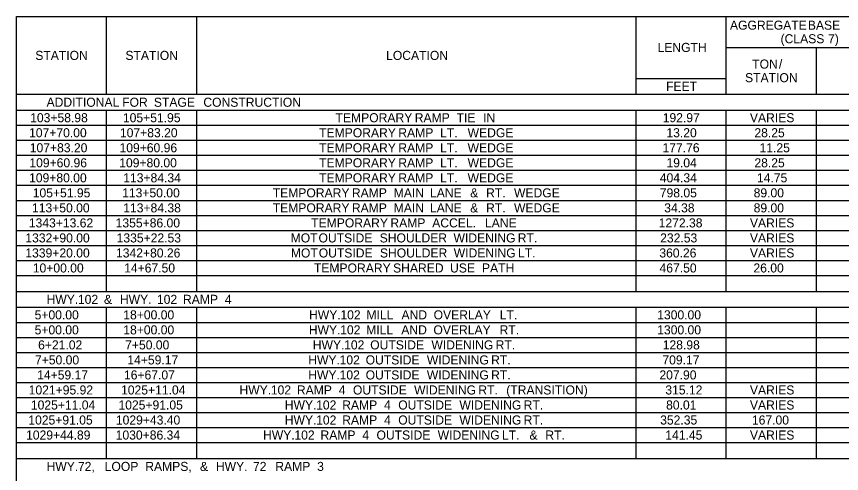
# Model space of a CAD drawing. Extents: x 1226567 to 1228151, y 151309 to 152305.
# Drawn here: x 1226566.8 to 1226930.3, y 152053.3 to 152254.7 of the extents above; entities that cross this region are included whole.
import ezdxf

# ---------------------------------------------------------------- set-up
doc = ezdxf.new("R2010")
doc.units = 0
doc.layers.add('R_Dimension', color=7, linetype='Continuous')

msp = doc.modelspace()

# ---------------------------------------------------------------- linework, layer by layer
at = {"layer": 'R_Dimension'}
for p, q in [((1226566.84, 152254.68), (1228150.79, 152254.68)), ((1226566.84, 151664.64), (1226566.84, 152254.68)), ((1226606.57, 152220.4), (1226606.57, 152254.68)), ((1226646.29, 152220.4), (1226646.29, 152254.68)), ((1226839.86, 152220.4), (1226839.86, 152254.68)), ((1226879.58, 152220.4), (1226879.58, 152254.68)), ((1226879.58, 152241.04), (1228150.79, 152241.04)), ((1226919.31, 152220.4), (1226919.31, 152241.04)), ((1226839.86, 152227.41), (1226879.58, 152227.41)), ((1226566.84, 152220.4), (1228150.79, 152220.4)), ((1226566.84, 152220.4), (1228150.79, 152220.4)), ((1226879.58, 152220.4), (1226998.76, 152220.4)), ((1226566.84, 152213.39), (1228150.79, 152213.39)), ((1226606.57, 152133.55), (1226606.57, 152213.39)), ((1226646.29, 152133.55), (1226646.29, 152213.39)), ((1226839.86, 152133.55), (1226839.86, 152213.39)), ((1226879.58, 152133.55), (1226879.58, 152213.39)), ((1226919.31, 152133.55), (1226919.31, 152213.39)), ((1226566.84, 152206.77), (1228150.79, 152206.77)), ((1226566.84, 152200.15), (1228150.79, 152200.15)), ((1226566.84, 152193.53), (1228150.79, 152193.53)), ((1226566.84, 152186.91), (1228150.79, 152186.91)), ((1226566.84, 152180.29), (1228150.79, 152180.29)), ((1226566.84, 152173.67), (1228150.79, 152173.67)), ((1226566.84, 152167.05), (1228150.79, 152167.05)), ((1226566.84, 152160.43), (1228150.79, 152160.43)), ((1226566.84, 152153.8), (1228150.79, 152153.8)), ((1226566.84, 152147.18), (1228150.79, 152147.18)), ((1226566.84, 152140.56), (1228150.79, 152140.56)), ((1226566.84, 152133.55), (1228150.79, 152133.55)), ((1226566.84, 152126.54), (1228150.79, 152126.54)), ((1226606.57, 152059.94), (1226606.57, 152126.54)), ((1226646.29, 152059.94), (1226646.29, 152126.54)), ((1226839.86, 152059.94), (1226839.86, 152126.54)), ((1226879.58, 152059.94), (1226879.58, 152126.54)), ((1226919.31, 152059.94), (1226919.31, 152126.54)), ((1226566.84, 152119.92), (1228150.79, 152119.92)), ((1226566.84, 152113.3), (1228150.79, 152113.3)), ((1226566.84, 152106.68), (1228150.79, 152106.68)), ((1226566.84, 152100.06), (1228150.79, 152100.06)), ((1226566.84, 152093.44), (1228150.79, 152093.44)), ((1226566.84, 152086.82), (1228150.79, 152086.82)), ((1226566.84, 152080.2), (1228150.79, 152080.2)), ((1226566.84, 152073.58), (1228150.79, 152073.58)), ((1226566.84, 152066.95), (1228150.79, 152066.95)), ((1226566.84, 152059.94), (1228150.79, 152059.94))]:
    msp.add_line(p, q, dxfattribs=at)

# ---------------------------------------------------------------- texts
for s, height, p in [('AGGREGATE', 3.994, (1226881.19, 152248.86)), (' BASE', 3.994, (1226914.02, 152248.86)), ('(CLASS', 3.994, (1226903.49, 152242.87)), (' 7)', 3.994, (1226922.92, 152242.87)), ('LENGTH', 3.994, (1226849.28, 152239.05)), ('STATION', 3.994, (1226575.12, 152235.54)), ('STATION', 3.994, (1226614.84, 152235.54)), ('LOCATION', 3.994, (1226729.69, 152235.54)), ('TON', 3.994, (1226891, 152231.72)), (' /', 3.994, (1226901.28, 152231.72)), ('STATION', 3.994, (1226887.85, 152225.73)), ('FEET', 3.994, (1226853.04, 152221.91)), ('ADDITIONAL', 3.994, (1226580.09, 152214.9)), (' FOR', 3.994, (1226611.92, 152214.9)), (' STAGE', 3.994, (1226625.88, 152214.9)), (' CONSTRUCTION', 3.9945, (1226647.68, 152214.9)), ('103+58.98', 3.994, (1226572.87, 152208.08)), ('105+51.95', 3.994, (1226613.73, 152208.08)), ('TEMPORARY', 3.994, (1226707.42, 152208.08)), (' RAMP', 3.994, (1226740.83, 152208.08)), (' TIE', 3.994, (1226759.26, 152208.08)), (' IN', 3.994, (1226770.93, 152208.08)), ('192.97', 3.994, (1226851.57, 152208.08)), ('VARIES', 3.994, (1226889.98, 152208.08)), ('107+70.00', 3.994, (1226572.38, 152201.46)), ('107+83.20', 3.994, (1226612.42, 152201.46)), ('TEMPORARY', 3.994, (1226700.17, 152201.46)), (' RAMP', 3.994, (1226733.58, 152201.46)), (' LT.', 3.994, (1226752.01, 152201.46)), (' WEDGE', 3.994, (1226764.12, 152201.46)), ('13.20', 3.994, (1226853.19, 152201.46)), ('28.25', 3.994, (1226891.96, 152201.46)), ('107+83.20', 3.994, (1226572.69, 152194.84)), ('109+60.96', 3.994, (1226612.23, 152194.84)), ('TEMPORARY', 3.994, (1226700.17, 152194.84)), (' RAMP', 3.994, (1226733.58, 152194.84)), (' LT.', 3.994, (1226752.01, 152194.84)), (' WEDGE', 3.994, (1226764.12, 152194.84)), ('177.76', 3.994, (1226851.46, 152194.84)), ('11.25', 3.994, (1226894.22, 152194.84)), ('109+60.96', 3.994, (1226572.51, 152188.22)), ('109+80.00', 3.994, (1226612.11, 152188.22)), ('TEMPORARY', 3.994, (1226700.17, 152188.22)), (' RAMP', 3.994, (1226733.58, 152188.22)), (' LT.', 3.994, (1226752.01, 152188.22)), (' WEDGE', 3.994, (1226764.12, 152188.22)), ('19.04', 3.994, (1226853.21, 152188.22)), ('28.25', 3.994, (1226891.96, 152188.22)), ('109+80.00', 3.994, (1226572.38, 152181.6)), ('113+84.34', 3.994, (1226613.88, 152181.6)), ('TEMPORARY', 3.994, (1226700.17, 152181.6)), (' RAMP', 3.994, (1226733.58, 152181.6)), (' LT.', 3.994, (1226752.01, 152181.6)), (' WEDGE', 3.994, (1226764.12, 152181.6)), ('404.34', 3.994, (1226850.28, 152181.6)), ('14.75', 3.994, (1226893.09, 152181.6)), ('105+51.95', 3.994, (1226574, 152174.98)), ('113+50.00', 3.994, (1226613.39, 152174.98)), ('TEMPORARY', 3.994, (1226679.73, 152174.98)), (' RAMP', 3.994, (1226713.13, 152174.98)), (' MAIN', 3.994, (1226731.56, 152174.98)), (' LANE', 3.994, (1226747.54, 152174.98)), (' &', 3.994, (1226765.25, 152174.98)), (' RT.', 3.994, (1226772.26, 152174.98)), (' WEDGE', 3.994, (1226784.56, 152174.98)), ('798.05', 3.994, (1226850.28, 152174.98)), ('89.00', 3.994, (1226891.63, 152174.98)), ('113+50.00', 3.994, (1226573.67, 152168.36)), ('113+84.38', 3.994, (1226613.88, 152168.36)), ('TEMPORARY', 3.994, (1226679.73, 152168.36)), (' RAMP', 3.994, (1226713.13, 152168.36)), (' MAIN', 3.994, (1226731.56, 152168.36)), (' LANE', 3.994, (1226747.54, 152168.36)), (' &', 3.994, (1226765.25, 152168.36)), (' RT.', 3.994, (1226772.26, 152168.36)), (' WEDGE', 3.994, (1226784.56, 152168.36)), ('34.38', 3.994, (1226852.23, 152168.36)), ('89.00', 3.994, (1226891.63, 152168.36)), ('1343+13.62', 3.994, (1226572.27, 152161.74)), ('1355+86.00', 3.994, (1226610.53, 152161.74)), ('TEMPORARY', 3.994, (1226696.68, 152161.74)), (' RAMP', 3.994, (1226730.09, 152161.74)), (' ACCEL.', 3.994, (1226748.52, 152161.74)), (' LANE', 3.994, (1226771.76, 152161.74)), ('1272.38', 3.994, (1226849.78, 152161.74)), ('VARIES', 3.994, (1226889.98, 152161.74)), ('1332+90.00', 3.994, (1226570.74, 152155.12)), ('1335+22.53', 3.994, (1226610.96, 152155.12)), ('MOT', 3.994, (1226687.64, 152155.12)), (' OUTSIDE', 3.994, (1226698.43, 152155.12)), (' SHOULDER', 3.994, (1226725.38, 152155.12)), (' WIDENING', 3.994, (1226757.91, 152155.12)), (' RT.', 3.994, (1226786.21, 152155.12)), ('232.53', 3.994, (1226850.44, 152155.12)), ('VARIES', 3.994, (1226889.98, 152155.12)), ('1339+20.00', 3.994, (1226570.74, 152148.5)), ('1342+80.26', 3.994, (1226610.69, 152148.5)), ('MOT', 3.994, (1226687.73, 152148.5)), (' OUTSIDE', 3.994, (1226698.52, 152148.5)), (' SHOULDER', 3.994, (1226725.48, 152148.5)), (' WIDENING', 3.994, (1226758, 152148.5)), (' LT.', 3.994, (1226786.31, 152148.5)), ('360.26', 3.994, (1226850.08, 152148.5)), ('VARIES', 3.994, (1226889.98, 152148.5)), ('10+00.00', 3.994, (1226574.02, 152141.88)), ('14+67.50', 3.994, (1226614.28, 152141.88)), ('TEMPORARY', 3.994, (1226697.88, 152141.88)), (' SHARED', 3.994, (1226731.28, 152141.88)), (' USE', 3.994, (1226756.38, 152141.88)), (' PATH', 3.994, (1226770.44, 152141.88)), ('467.50', 3.994, (1226850.17, 152141.88)), ('26.00', 3.994, (1226891.53, 152141.88)), ('HWY.', 3.994, (1226580.09, 152128.05)), (' 102', 3.994, (1226592.42, 152128.05)), (' &', 3.994, (1226603.9, 152128.05)), (' HWY.', 3.994, (1226610.91, 152128.05)), (' 102', 3.994, (1226627.23, 152128.05)), (' RAMP', 3.994, (1226638.71, 152128.05)), (' 4', 3.994, (1226657.14, 152128.05)), ('5+00.00', 3.994, (1226574.83, 152121.23)), ('18+00.00', 3.994, (1226613.9, 152121.23)), ('HWY.', 3.994, (1226695.74, 152121.23)), (' 102', 3.994, (1226708.07, 152121.23)), (' MILL', 3.994, (1226719.55, 152121.23)), (' AND', 3.994, (1226734.99, 152121.23)), (' OVERLAY', 3.994, (1226749.15, 152121.23)), (' LT.', 3.994, (1226778.3, 152121.23)), ('1300.00', 3.994, (1226849.14, 152121.23)), ('5+00.00', 3.994, (1226574.83, 152114.61)), ('18+00.00', 3.994, (1226613.9, 152114.61)), ('HWY.', 3.994, (1226695.65, 152114.61)), (' 102', 3.994, (1226707.97, 152114.61)), (' MILL', 3.994, (1226719.45, 152114.61)), (' AND', 3.994, (1226734.9, 152114.61)), (' OVERLAY', 3.994, (1226749.05, 152114.61)), (' RT.', 3.994, (1226778.21, 152114.61)), ('1300.00', 3.994, (1226849.14, 152114.61)), ('6+21.02', 3.994, (1226576.36, 152107.99)), ('7+50.00', 3.994, (1226614.72, 152107.99)), ('HWY.', 3.994, (1226697.39, 152107.99)), (' 102', 3.994, (1226709.72, 152107.99)), (' OUTSIDE', 3.994, (1226721.2, 152107.99)), (' WIDENING', 3.994, (1226748.16, 152107.99)), (' RT.', 3.994, (1226776.46, 152107.99)), ('128.98', 3.994, (1226851.57, 152107.99)), ('7+50.00', 3.994, (1226574.99, 152101.37)), ('14+59.17', 3.994, (1226615.68, 152101.37)), ('HWY.', 3.994, (1226695.39, 152101.37)), (' 102', 3.994, (1226707.72, 152101.37)), (' OUTSIDE', 3.994, (1226719.2, 152101.37)), (' WIDENING', 3.994, (1226746.16, 152101.37)), (' RT.', 3.994, (1226774.47, 152101.37)), ('709.17', 3.994, (1226851.42, 152101.37)), ('14+59.17', 3.994, (1226575.95, 152094.75)), ('16+67.07', 3.994, (1226614.2, 152094.75)), ('HWY.', 3.994, (1226695.39, 152094.75)), (' 102', 3.994, (1226707.72, 152094.75)), (' OUTSIDE', 3.994, (1226719.2, 152094.75)), (' WIDENING', 3.994, (1226746.16, 152094.75)), (' RT.', 3.994, (1226774.47, 152094.75)), ('207.90', 3.994, (1226850.11, 152094.75)), ('1021+95.92', 3.994, (1226572.21, 152088.13)), ('1025+11.04', 3.994, (1226612.91, 152088.13)), ('HWY.', 3.994, (1226665.09, 152088.13)), (' 102', 3.994, (1226677.42, 152088.13)), (' RAMP', 3.994, (1226688.9, 152088.13)), (' 4', 3.994, (1226707.33, 152088.13)), (' OUTSIDE', 3.994, (1226713.59, 152088.13)), (' WIDENING', 3.994, (1226740.54, 152088.13)), (' RT.', 3.994, (1226768.85, 152088.13)), (' (TRANSITION)', 3.9945, (1226781.15, 152088.13)), ('315.12', 3.994, (1226852.71, 152088.13)), ('VARIES', 3.994, (1226889.98, 152088.13)), ('1025+11.04', 3.994, (1226573.18, 152081.51)), ('1025+91.05', 3.994, (1226611.77, 152081.51)), ('HWY.', 3.994, (1226685.05, 152081.51)), (' 102', 3.994, (1226697.38, 152081.51)), (' RAMP', 3.994, (1226708.86, 152081.51)), (' 4', 3.994, (1226727.29, 152081.51)), (' OUTSIDE', 3.994, (1226733.55, 152081.51)), (' WIDENING', 3.994, (1226760.5, 152081.51)), (' RT.', 3.994, (1226788.81, 152081.51)), ('80.01', 3.994, (1226853.05, 152081.51)), ('VARIES', 3.994, (1226889.98, 152081.51)), ('1025+91.05', 3.994, (1226572.05, 152074.89)), ('1029+43.40', 3.994, (1226610.63, 152074.89)), ('HWY.', 3.994, (1226685.05, 152074.89)), (' 102', 3.994, (1226697.38, 152074.89)), (' RAMP', 3.994, (1226708.86, 152074.89)), (' 4', 3.994, (1226727.29, 152074.89)), (' OUTSIDE', 3.994, (1226733.55, 152074.89)), (' WIDENING', 3.994, (1226760.5, 152074.89)), (' RT.', 3.994, (1226788.81, 152074.89)), ('352.35', 3.994, (1226850.44, 152074.89)), ('167.00', 3.994, (1226890.87, 152074.89)), ('1029+44.89', 3.994, (1226571.06, 152068.27)), ('1030+86.34', 3.994, (1226610.55, 152068.27)), ('HWY.', 3.994, (1226675.48, 152068.27)), (' 102', 3.994, (1226687.81, 152068.27)), (' RAMP', 3.994, (1226699.29, 152068.27)), (' 4', 3.994, (1226717.73, 152068.27)), (' OUTSIDE', 3.994, (1226723.98, 152068.27)), (' WIDENING', 3.994, (1226750.94, 152068.27)), (' LT.', 3.994, (1226779.25, 152068.27)), (' &', 3.994, (1226791.36, 152068.27)), (' RT.', 3.994, (1226798.37, 152068.27)), ('141.45', 3.994, (1226852.71, 152068.27)), ('VARIES', 3.994, (1226889.98, 152068.27)), ('HWY.', 3.994, (1226580.09, 152054.44)), (' 72,', 3.994, (1226592.42, 152054.44)), (' LOOP', 3.994, (1226604.21, 152054.44)), (' RAMPS,', 3.994, (1226622.08, 152054.44)), (' &', 3.994, (1226646.2, 152054.44)), (' HWY.', 3.994, (1226653.21, 152054.44)), (' 72', 3.994, (1226669.54, 152054.44)), (' RAMP', 3.994, (1226679.38, 152054.44)), (' 3', 3.994, (1226697.81, 152054.44))]:
    msp.add_text(s, height=height, dxfattribs=at).set_placement(p)

doc.saveas('drawing.dxf')
